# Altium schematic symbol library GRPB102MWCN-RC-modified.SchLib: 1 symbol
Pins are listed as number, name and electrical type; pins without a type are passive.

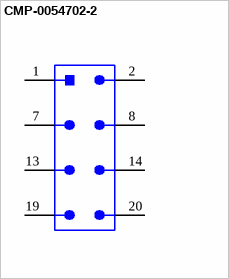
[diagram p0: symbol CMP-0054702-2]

## CMP-0054702-2
designator J?, comment GRPB102MWCN-RC
Header, 50mil, 10x2, Gold, R/A, TH; Manufacturer: Sullins Connector Solutions
footprint Sullins_GRPB102MWCN-modified (SULLINS)
pins: 1, 2, 7, 8, 13, 14, 19, 20
1 alternate drawing of the same symbol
